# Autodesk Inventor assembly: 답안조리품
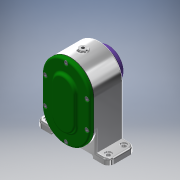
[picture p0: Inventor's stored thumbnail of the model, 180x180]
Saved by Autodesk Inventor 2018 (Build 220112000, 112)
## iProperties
Created: 2021-05
Part Number: 답안조리품
Material: 일반
Document SubType Name: Assembly
Designer: Admin
Author: Admin
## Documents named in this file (19)
- C:\Users\Admin\Desktop\710509V1016\답안조리품.iam
- C:\Users\Admin\Desktop\710509V1016\본체.ipt
- C:\Users\Admin\Desktop\710509V1016\축 A.ipt
- C:\Users\Admin\Desktop\710509V1016\베어링 6001.ipt
- 베어링 6001.ipt
- C:\Users\Admin\Desktop\710509V1016\베어링 6002.ipt
- 베어링 6002.ipt
- C:\Users\Admin\Desktop\710509V1016\칼라.ipt
- C:\Users\Admin\Desktop\710509V1016\키 5 x 5 x 12.ipt
- C:\Users\Admin\Desktop\710509V1016\스퍼기어 A.ipt
- C:\Users\Admin\Desktop\710509V1016\커버 B.ipt
- C:\Users\Admin\Desktop\710509V1016\오일 실 12 22 7.ipt
- C:\Users\Admin\Desktop\710509V1016\축 B.ipt
- C:\Users\Admin\Desktop\710509V1016\키 4 x 4 x 12.ipt
- C:\Users\Admin\Desktop\710509V1016\스퍼기어 B.ipt
- C:\Users\Admin\Desktop\710509V1016\개스킷 A.ipt
- C:\Users\Admin\Desktop\710509V1016\개스킷 B.ipt
- C:\Users\Admin\Desktop\710509V1016\커버 A.ipt
- C:\Users\Admin\Desktop\710509V1016\볼트 M4.ipt
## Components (2 placed, 2 different names)
1. 개스킷 A:1
2. 개스킷 B:1
